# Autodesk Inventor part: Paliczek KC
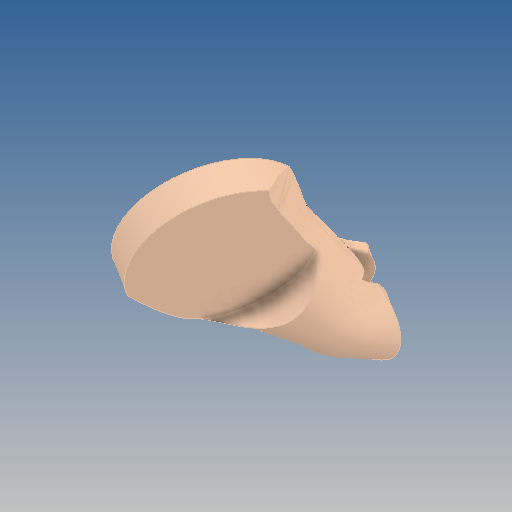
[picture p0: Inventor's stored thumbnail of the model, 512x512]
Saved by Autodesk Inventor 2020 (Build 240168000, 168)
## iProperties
Created: 2019-10
Part Number: Paliczek KC
Material: GFRP
Document SubType Name: Modeling
Designer: yello
Density: 1.75 g/cm^3
Appearance: Default
Author: yello
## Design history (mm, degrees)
feature "Paliczek KC"
body "Solid1"
